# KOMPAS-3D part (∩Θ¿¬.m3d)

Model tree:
1. Эскиз:1
2. Операция выдавливания:1
     Расстояние 1 = 43.4; Расстояние 2 = 1
3. Эскиз:2
4. Вырезать элемент выдавливания:1
     Расстояние 1 = 27
5. Эскиз:3
6. Вырезать элемент выдавливания:2
     Расстояние 1 = 43.4
7. Эскиз:4
8. Операция выдавливания:2
     Расстояние 1 = 2; Расстояние 2 = 1
9. Эскиз:5
10. Операция выдавливания:3
     Расстояние 1 = 7; Расстояние 2 = 1
11. Эскиз:6
12. Вырезать элемент выдавливания:3
     Расстояние 1 = 35.3148
13. Эскиз:7
14. Вырезать элемент выдавливания:4
     Расстояние 1 = 35.3148
15. Зеркальный массив:1  (with: Операция выдавливания:1, Вырезать элемент выдавливания:1, Вырезать элемент выдавливания:2, Операция выдавливания:2, Операция выдавливания:3, Вырезать элемент выдавливания:3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)  (labels: Экземпляр ( 1 ); Экземпляр ( 2 ))
16. Скругление:1
     Радиус = 0.3
17. Скругление:2
     Радиус = 0.3
18. Скругление:3
     Радиус = 0.3
19. Скругление:4
     Радиус = 1
20. Скругление:5
     Радиус = 1
21. Скругление:6
     Радиус = 1
22. Скругление:7
     Радиус = 0.5
23. Эскиз:9
24. Вырезать элемент выдавливания:6
     Расстояние 1 = 0.3
25. Эскиз:10
26. Вырезать элемент выдавливания:7
     Расстояние 1 = 0.3
27. Эскиз:11
28. Вырезать элемент выдавливания:8
     Расстояние 1 = 0.3
29. Эскиз:12
30. Операция выдавливания:4
     Расстояние 1 = 0.3; Расстояние 2 = 1
31. Скругление:8
     Радиус = 0.3
32. Скругление:9
     Радиус = 0.3
33. Скругление:10
     Радиус = 0.3

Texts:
  Сплав АЛ8  ГОСТ 1583-93
  Экземпляр ( 1 )
  Экземпляр ( 2 )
